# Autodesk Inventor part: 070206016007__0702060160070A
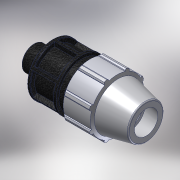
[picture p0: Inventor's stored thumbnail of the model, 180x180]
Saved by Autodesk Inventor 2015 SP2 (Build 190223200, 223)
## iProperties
Created: 2017-02
Part Number: 070206016007__0702060160070A
Material: PVC-Piping
Description: PLASSON MALE ADAPTOR 16-3/4"
Document SubType Name: Modeling
Designer: KIM
Mass: 92.6774 g
Surface Area: 199.44 cm^2
Volume: 66.1981 cm^3
Density: 1.4 g/cm^3
Appearance: PTFE
Author: KIM
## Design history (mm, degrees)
derived "07020.ipt"
feature "Solid1::07020.ipt"
tag "TaggingFeature1"
body "Solid1"
other parameters: "d2" = 16, "d4" = 11.28571, "d5" = 19.75, "d7" = 39, "d8" = 29.25, "d9" = 11.28571, "d11" = 2.25714, "d12" = 31.2, "d13" = 120 deg, "d14" = 24, "d15" = 12 deg, "d16" = 35.1, "d18" = 0.8, "d19" = 35 deg, "d20" = 17.5 deg, "d21" = 36.27, "d23" = 0, "d25" = 360 deg, "d27" = 0.78, "d34" = 1.95, "d36" = 0, "d42" = 19.75, "d43" = 1.17, "d46" = 0.48, "d49" = 59, "d51" = 79, "d52" = 17, "d53" = 0.32, "d55" = 360 deg, "d57" = 26.441, "d58" = 18.5087, "d59" = 15.8, "d_" = 16, "E_" = 39, "H_" = 79, "l_" = 59, "l_2" = 17, "R_" = 26.441
